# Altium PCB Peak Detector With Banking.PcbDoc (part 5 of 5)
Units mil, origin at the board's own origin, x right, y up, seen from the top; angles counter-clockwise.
Board outline 3330 x 2725 mil, 4 copper layers (TopLayer, GROUND, MidLayer1, BottomLayer); 549 components, 391 nets, 1594 pads, 460 vias.
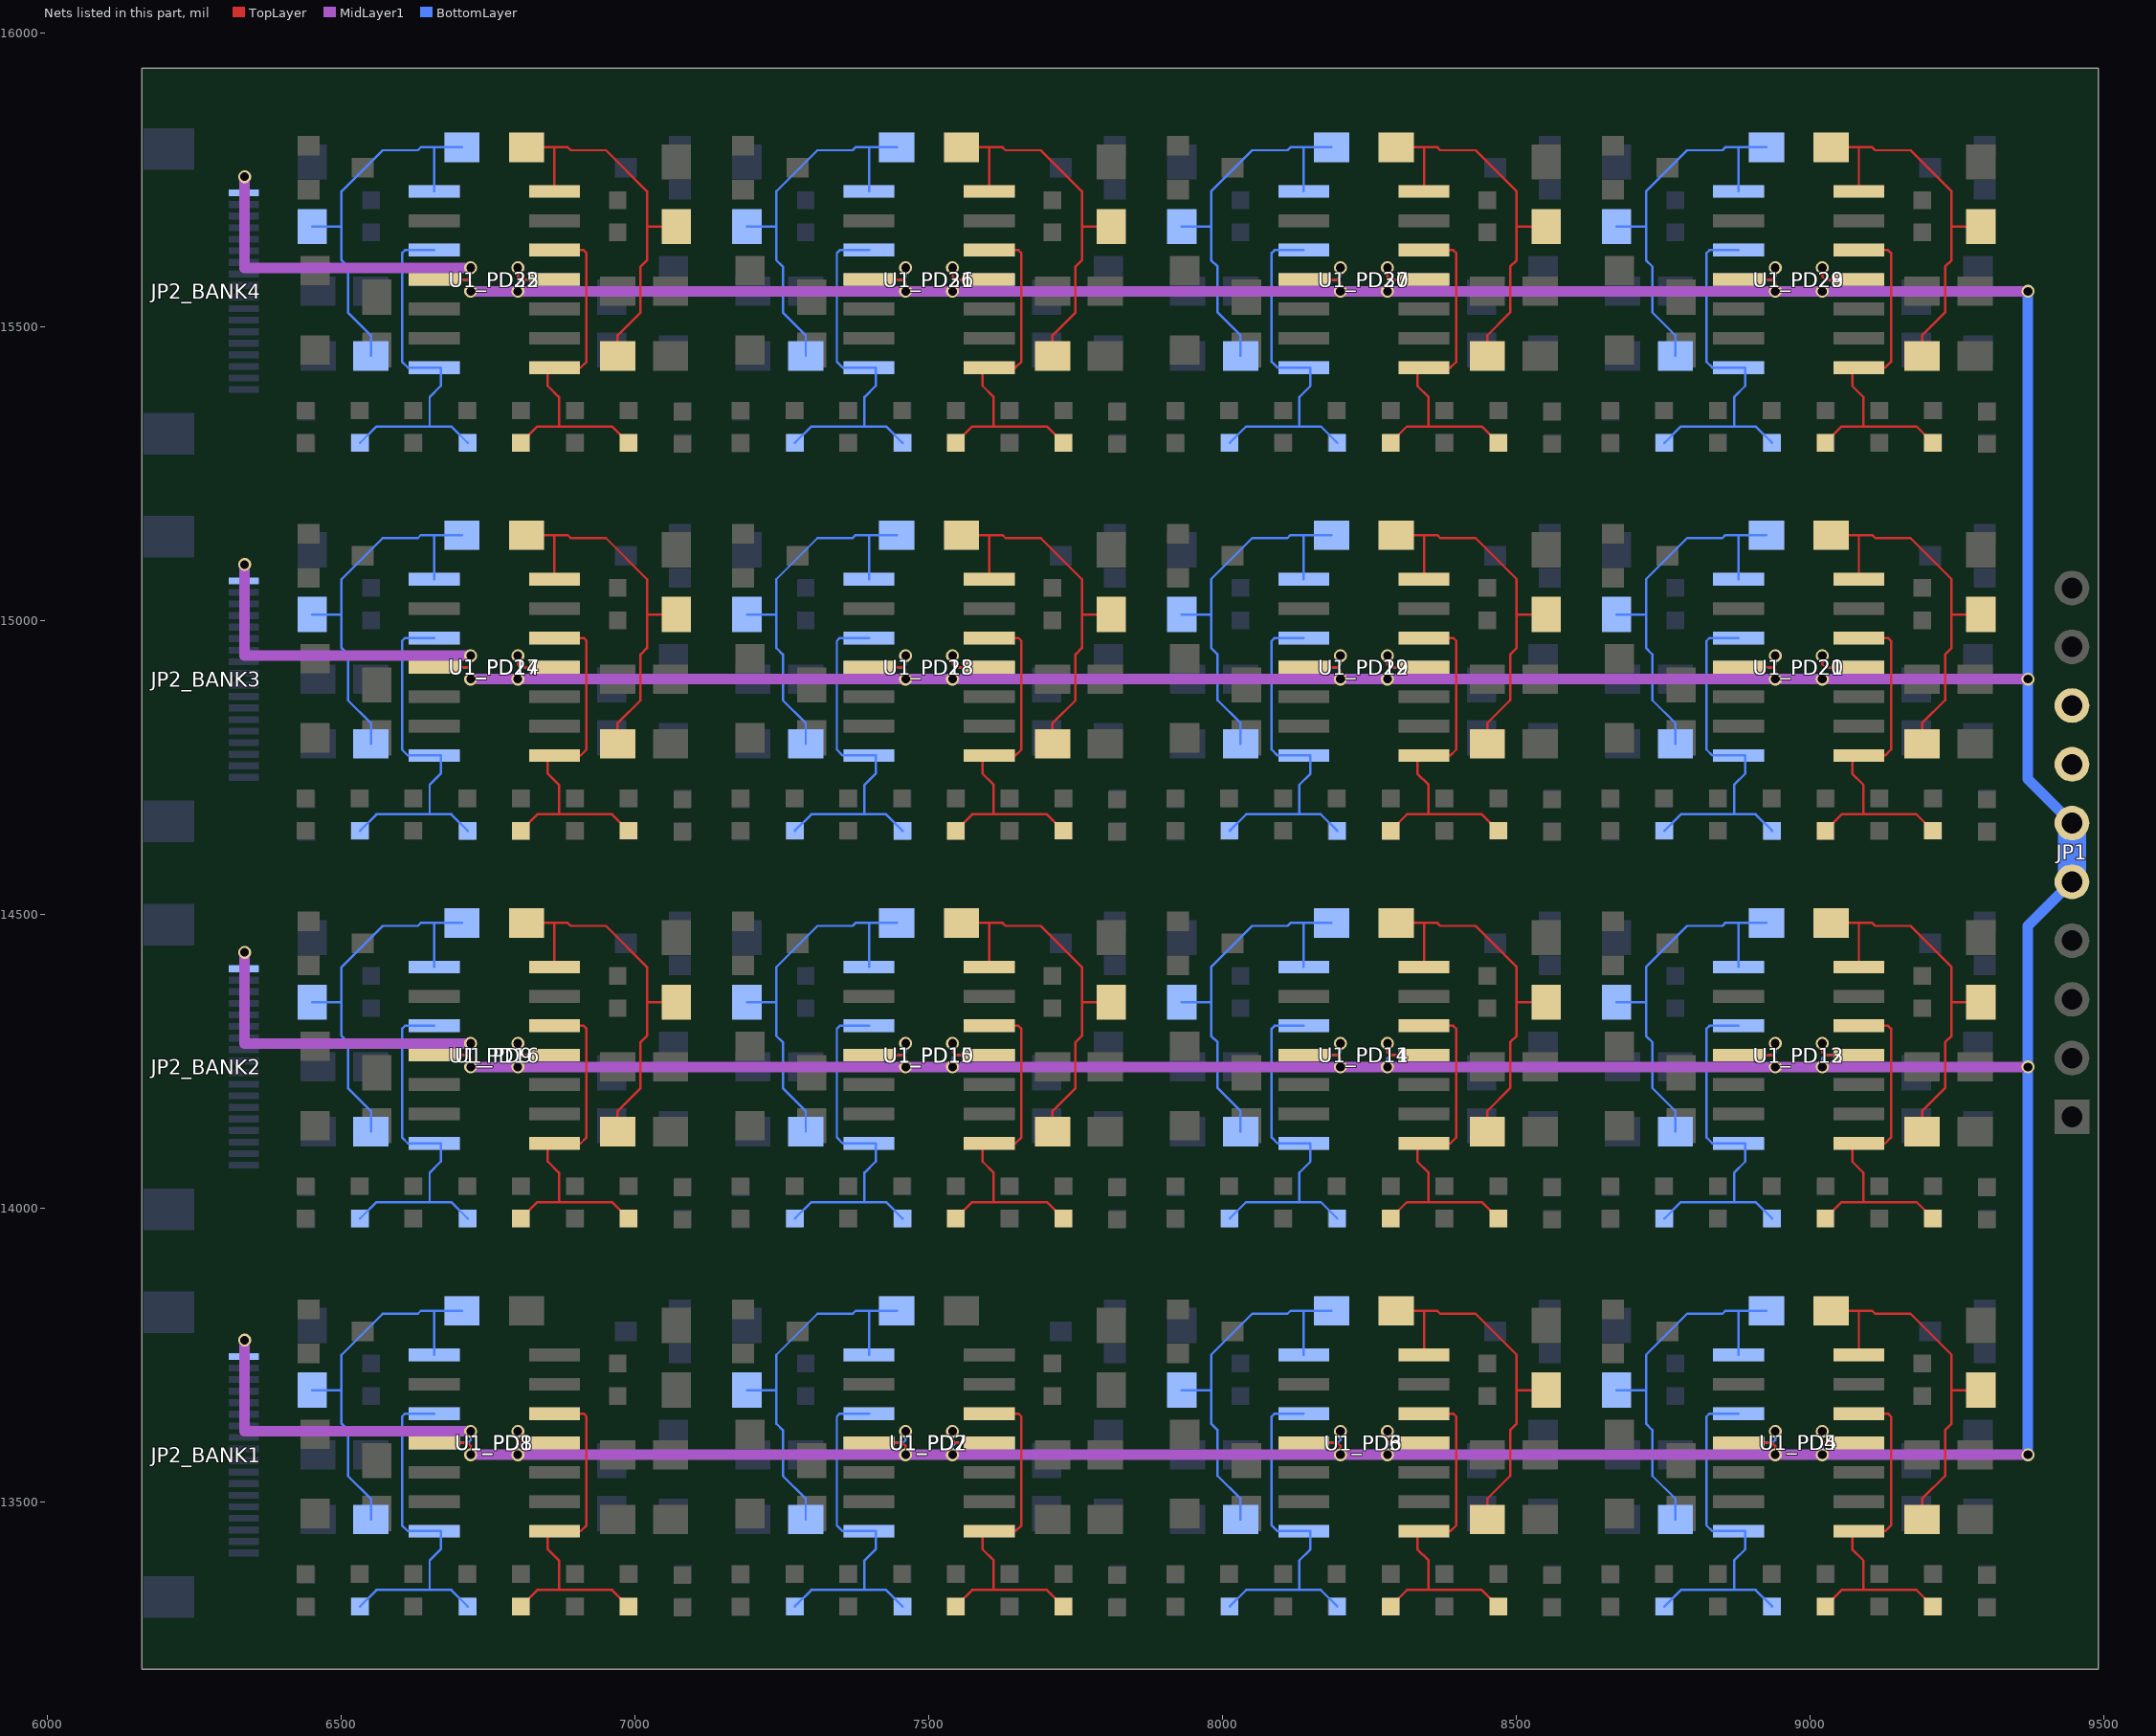
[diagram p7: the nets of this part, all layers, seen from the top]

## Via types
v1: diameter 22, hole 15, TopLayer to BottomLayer, 432 vias
v2: diameter 22, hole 16, TopLayer to BottomLayer, 28 vias

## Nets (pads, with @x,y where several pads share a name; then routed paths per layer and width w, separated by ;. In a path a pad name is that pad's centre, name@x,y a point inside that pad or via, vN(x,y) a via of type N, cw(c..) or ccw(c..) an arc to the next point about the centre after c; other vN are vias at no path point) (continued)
S_DIODE_PD3: C4_PD3.2 D1_PD3.1 D2_PD3.2 U1_PD3.7 | length 661.7
  TopLayer w4: D1_PD3.1@8295.01,13825 8342.35,13825 ; U1_PD3.7@8342.35,13750 8342.35,13825 ; C4_PD3.2@8449.99,13470 8449.99,13504.99 8489,13544 8489,13622 8500,13633 8500,13690 ; D2_PD3.2@8550,13690.01 8500.01,13690.01 ; 8342.35,13825 8365,13825 8370,13820 8430,13820 8500,13750 8500,13690.02
S_DIODE_PD4: C4_PD4.2 D1_PD4.1 D2_PD4.2 U1_PD4.7 | length 661.7
  TopLayer w4: D1_PD4.1@9035.01,13825 9082.35,13825 ; U1_PD4.7@9082.35,13750 9082.35,13825 ; C4_PD4.2@9189.99,13470 9189.99,13504.99 9229,13544 9229,13622 9240,13633 9240,13690 ; D2_PD4.2@9290,13690.01 9240.01,13690.01 ; 9082.35,13825 9105,13825 9110,13820 9170,13820 9240,13750 9240,13690.02
S_DIODE_PD5: C4_PD5.2 D1_PD5.1 D2_PD5.2 U1_PD5.7 | length 661.7
  BottomLayer w4: D2_PD5.2@8670,13690.01 8719.99,13690.01 ; C4_PD5.2@8770.01,13470 8770.01,13504.99 8731,13544 8731,13622 8720,13633 8720,13690 ; U1_PD5.7@8877.65,13750 8877.65,13825 ; D1_PD5.1@8924.99,13825 8877.65,13825 ; 8720,13690.02 8720,13750 8790,13820 8850,13820 8855,13825 8877.65,13825
S_DIODE_PD6: C4_PD6.2 D1_PD6.1 D2_PD6.2 U1_PD6.7 | length 661.7
  BottomLayer w4: D2_PD6.2@7930,13690.01 7979.99,13690.01 ; C4_PD6.2@8030.01,13470 8030.01,13504.99 7991,13544 7991,13622 7980,13633 7980,13690 ; U1_PD6.7@8137.65,13750 8137.65,13825 ; D1_PD6.1@8184.99,13825 8137.65,13825 ; 7980,13690.02 7980,13750 8050,13820 8110,13820 8115,13825 8137.65,13825
S_DIODE_PD7: C4_PD7.2 D1_PD7.1 D2_PD7.2 U1_PD7.7 | length 661.7
  BottomLayer w4: D2_PD7.2@7190,13690.01 7239.99,13690.01 ; C4_PD7.2@7290.01,13470 7290.01,13504.99 7251,13544 7251,13622 7240,13633 7240,13690 ; U1_PD7.7@7397.65,13750 7397.65,13825 ; D1_PD7.1@7444.99,13825 7397.65,13825 ; 7240,13690.02 7240,13750 7310,13820 7370,13820 7375,13825 7397.65,13825
S_DIODE_PD8: C4_PD8.2 D1_PD8.1 D2_PD8.2 U1_PD8.7 | length 661.7
  BottomLayer w4: D2_PD8.2@6450,13690.01 6499.99,13690.01 ; C4_PD8.2@6550.01,13470 6550.01,13504.99 6511,13544 6511,13622 6500,13633 6500,13690 ; U1_PD8.7@6657.65,13750 6657.65,13825 ; D1_PD8.1@6704.99,13825 6657.65,13825 ; 6500,13690.02 6500,13750 6570,13820 6630,13820 6635,13825 6657.65,13825
S_DIODE_PD9: C4_PD9.2 D1_PD9.1 D2_PD9.2 U1_PD9.7 | length 661.7
  TopLayer w4: D1_PD9.1@6815.01,14485 6862.35,14485 ; U1_PD9.7@6862.35,14410 6862.35,14485 ; C4_PD9.2@6969.99,14130 6969.99,14164.99 7009,14204 7009,14282 7020,14293 7020,14350 ; D2_PD9.2@7070,14350.01 7020.01,14350.01 ; 6862.35,14485 6885,14485 6890,14480 6950,14480 7020,14410 7020,14350.02
S_DIODE_PD10: C4_PD10.2 D1_PD10.1 D2_PD10.2 U1_PD10.7 | length 661.7
  TopLayer w4: D1_PD10.1@7555.01,14485 7602.35,14485 ; U1_PD10.7@7602.35,14410 7602.35,14485 ; C4_PD10.2@7709.99,14130 7709.99,14164.99 7749,14204 7749,14282 7760,14293 7760,14350 ; D2_PD10.2@7810,14350.01 7760.01,14350.01 ; 7602.35,14485 7625,14485 7630,14480 7690,14480 7760,14410 7760,14350.02
S_DIODE_PD11: C4_PD11.2 D1_PD11.1 D2_PD11.2 U1_PD11.7 | length 661.7
  TopLayer w4: D1_PD11.1@8295.01,14485 8342.35,14485 ; U1_PD11.7@8342.35,14410 8342.35,14485 ; C4_PD11.2@8449.99,14130 8449.99,14164.99 8489,14204 8489,14282 8500,14293 8500,14350 ; D2_PD11.2@8550,14350.01 8500.01,14350.01 ; 8342.35,14485 8365,14485 8370,14480 8430,14480 8500,14410 8500,14350.02
S_DIODE_PD12: C4_PD12.2 D1_PD12.1 D2_PD12.2 U1_PD12.7 | length 661.7
  TopLayer w4: D1_PD12.1@9035.01,14485 9082.35,14485 ; U1_PD12.7@9082.35,14410 9082.35,14485 ; C4_PD12.2@9189.99,14130 9189.99,14164.99 9229,14204 9229,14282 9240,14293 9240,14350 ; D2_PD12.2@9290,14350.01 9240.01,14350.01 ; 9082.35,14485 9105,14485 9110,14480 9170,14480 9240,14410 9240,14350.02
S_DIODE_PD13: C4_PD13.2 D1_PD13.1 D2_PD13.2 U1_PD13.7 | length 661.7
  BottomLayer w4: D2_PD13.2@8670,14350.01 8719.99,14350.01 ; C4_PD13.2@8770.01,14130 8770.01,14164.99 8731,14204 8731,14282 8720,14293 8720,14350 ; U1_PD13.7@8877.65,14410 8877.65,14485 ; D1_PD13.1@8924.99,14485 8877.65,14485 ; 8720,14350.02 8720,14410 8790,14480 8850,14480 8855,14485 8877.65,14485
S_DIODE_PD14: C4_PD14.2 D1_PD14.1 D2_PD14.2 U1_PD14.7 | length 661.7
  BottomLayer w4: D2_PD14.2@7930,14350.01 7979.99,14350.01 ; C4_PD14.2@8030.01,14130 8030.01,14164.99 7991,14204 7991,14282 7980,14293 7980,14350 ; U1_PD14.7@8137.65,14410 8137.65,14485 ; D1_PD14.1@8184.99,14485 8137.65,14485 ; 7980,14350.02 7980,14410 8050,14480 8110,14480 8115,14485 8137.65,14485
S_DIODE_PD15: C4_PD15.2 D1_PD15.1 D2_PD15.2 U1_PD15.7 | length 661.7
  BottomLayer w4: D2_PD15.2@7190,14350.01 7239.99,14350.01 ; C4_PD15.2@7290.01,14130 7290.01,14164.99 7251,14204 7251,14282 7240,14293 7240,14350 ; U1_PD15.7@7397.65,14410 7397.65,14485 ; D1_PD15.1@7444.99,14485 7397.65,14485 ; 7240,14350.02 7240,14410 7310,14480 7370,14480 7375,14485 7397.65,14485
S_DIODE_PD16: C4_PD16.2 D1_PD16.1 D2_PD16.2 U1_PD16.7 | length 661.7
  BottomLayer w4: D2_PD16.2@6450,14350.01 6499.99,14350.01 ; C4_PD16.2@6550.01,14130 6550.01,14164.99 6511,14204 6511,14282 6500,14293 6500,14350 ; U1_PD16.7@6657.65,14410 6657.65,14485 ; D1_PD16.1@6704.99,14485 6657.65,14485 ; 6500,14350.02 6500,14410 6570,14480 6630,14480 6635,14485 6657.65,14485
S_DIODE_PD17: C4_PD17.2 D1_PD17.1 D2_PD17.2 U1_PD17.7 | length 661.7
  TopLayer w4: D1_PD17.1@6815.01,15145 6862.35,15145 ; U1_PD17.7@6862.35,15070 6862.35,15145 ; C4_PD17.2@6969.99,14790 6969.99,14824.99 7009,14864 7009,14942 7020,14953 7020,15010 ; D2_PD17.2@7070,15010.01 7020.01,15010.01 ; 6862.35,15145 6885,15145 6890,15140 6950,15140 7020,15070 7020,15010.02
S_DIODE_PD18: C4_PD18.2 D1_PD18.1 D2_PD18.2 U1_PD18.7 | length 661.7
  TopLayer w4: D1_PD18.1@7555.01,15145 7602.35,15145 ; U1_PD18.7@7602.35,15070 7602.35,15145 ; C4_PD18.2@7709.99,14790 7709.99,14824.99 7749,14864 7749,14942 7760,14953 7760,15010 ; D2_PD18.2@7810,15010.01 7760.01,15010.01 ; 7602.35,15145 7625,15145 7630,15140 7690,15140 7760,15070 7760,15010.02
S_DIODE_PD19: C4_PD19.2 D1_PD19.1 D2_PD19.2 U1_PD19.7 | length 661.7
  TopLayer w4: D1_PD19.1@8295.01,15145 8342.35,15145 ; U1_PD19.7@8342.35,15070 8342.35,15145 ; C4_PD19.2@8449.99,14790 8449.99,14824.99 8489,14864 8489,14942 8500,14953 8500,15010 ; D2_PD19.2@8550,15010.01 8500.01,15010.01 ; 8342.35,15145 8365,15145 8370,15140 8430,15140 8500,15070 8500,15010.02
S_DIODE_PD20: C4_PD20.2 D1_PD20.1 D2_PD20.2 U1_PD20.7 | length 661.7
  TopLayer w4: D1_PD20.1@9035.01,15145 9082.35,15145 ; U1_PD20.7@9082.35,15070 9082.35,15145 ; C4_PD20.2@9189.99,14790 9189.99,14824.99 9229,14864 9229,14942 9240,14953 9240,15010 ; D2_PD20.2@9290,15010.01 9240.01,15010.01 ; 9082.35,15145 9105,15145 9110,15140 9170,15140 9240,15070 9240,15010.02
S_DIODE_PD21: C4_PD21.2 D1_PD21.1 D2_PD21.2 U1_PD21.7 | length 661.7
  BottomLayer w4: D2_PD21.2@8670,15010.01 8719.99,15010.01 ; C4_PD21.2@8770.01,14790 8770.01,14824.99 8731,14864 8731,14942 8720,14953 8720,15010 ; U1_PD21.7@8877.65,15070 8877.65,15145 ; D1_PD21.1@8924.99,15145 8877.65,15145 ; 8720,15010.02 8720,15070 8790,15140 8850,15140 8855,15145 8877.65,15145
S_DIODE_PD22: C4_PD22.2 D1_PD22.1 D2_PD22.2 U1_PD22.7 | length 661.7
  BottomLayer w4: D2_PD22.2@7930,15010.01 7979.99,15010.01 ; C4_PD22.2@8030.01,14790 8030.01,14824.99 7991,14864 7991,14942 7980,14953 7980,15010 ; U1_PD22.7@8137.65,15070 8137.65,15145 ; D1_PD22.1@8184.99,15145 8137.65,15145 ; 7980,15010.02 7980,15070 8050,15140 8110,15140 8115,15145 8137.65,15145
S_DIODE_PD23: C4_PD23.2 D1_PD23.1 D2_PD23.2 U1_PD23.7 | length 661.7
  BottomLayer w4: D2_PD23.2@7190,15010.01 7239.99,15010.01 ; C4_PD23.2@7290.01,14790 7290.01,14824.99 7251,14864 7251,14942 7240,14953 7240,15010 ; U1_PD23.7@7397.65,15070 7397.65,15145 ; D1_PD23.1@7444.99,15145 7397.65,15145 ; 7240,15010.02 7240,15070 7310,15140 7370,15140 7375,15145 7397.65,15145
S_DIODE_PD24: C4_PD24.2 D1_PD24.1 D2_PD24.2 U1_PD24.7 | length 661.7
  BottomLayer w4: D2_PD24.2@6450,15010.01 6499.99,15010.01 ; C4_PD24.2@6550.01,14790 6550.01,14824.99 6511,14864 6511,14942 6500,14953 6500,15010 ; U1_PD24.7@6657.65,15070 6657.65,15145 ; D1_PD24.1@6704.99,15145 6657.65,15145 ; 6500,15010.02 6500,15070 6570,15140 6630,15140 6635,15145 6657.65,15145
S_DIODE_PD25: C4_PD25.2 D1_PD25.1 D2_PD25.2 U1_PD25.7 | length 661.7
  TopLayer w4: D1_PD25.1@6815.01,15805 6862.35,15805 ; U1_PD25.7@6862.35,15730 6862.35,15805 ; C4_PD25.2@6969.99,15450 6969.99,15484.99 7009,15524 7009,15602 7020,15613 7020,15670 ; D2_PD25.2@7070,15670.01 7020.01,15670.01 ; 6862.35,15805 6885,15805 6890,15800 6950,15800 7020,15730 7020,15670.02
S_DIODE_PD26: C4_PD26.2 D1_PD26.1 D2_PD26.2 U1_PD26.7 | length 661.7
  TopLayer w4: D1_PD26.1@7555.01,15805 7602.35,15805 ; U1_PD26.7@7602.35,15730 7602.35,15805 ; C4_PD26.2@7709.99,15450 7709.99,15484.99 7749,15524 7749,15602 7760,15613 7760,15670 ; D2_PD26.2@7810,15670.01 7760.01,15670.01 ; 7602.35,15805 7625,15805 7630,15800 7690,15800 7760,15730 7760,15670.02
S_DIODE_PD27: C4_PD27.2 D1_PD27.1 D2_PD27.2 U1_PD27.7 | length 661.7
  TopLayer w4: D1_PD27.1@8295.01,15805 8342.35,15805 ; U1_PD27.7@8342.35,15730 8342.35,15805 ; C4_PD27.2@8449.99,15450 8449.99,15484.99 8489,15524 8489,15602 8500,15613 8500,15670 ; D2_PD27.2@8550,15670.01 8500.01,15670.01 ; 8342.35,15805 8365,15805 8370,15800 8430,15800 8500,15730 8500,15670.02
S_DIODE_PD28: C4_PD28.2 D1_PD28.1 D2_PD28.2 U1_PD28.7 | length 661.7
  TopLayer w4: D1_PD28.1@9035.01,15805 9082.35,15805 ; U1_PD28.7@9082.35,15730 9082.35,15805 ; C4_PD28.2@9189.99,15450 9189.99,15484.99 9229,15524 9229,15602 9240,15613 9240,15670 ; D2_PD28.2@9290,15670.01 9240.01,15670.01 ; 9082.35,15805 9105,15805 9110,15800 9170,15800 9240,15730 9240,15670.02
S_DIODE_PD29: C4_PD29.2 D1_PD29.1 D2_PD29.2 U1_PD29.7 | length 661.7
  BottomLayer w4: D2_PD29.2@8670,15670.01 8719.99,15670.01 ; C4_PD29.2@8770.01,15450 8770.01,15484.99 8731,15524 8731,15602 8720,15613 8720,15670 ; U1_PD29.7@8877.65,15730 8877.65,15805 ; D1_PD29.1@8924.99,15805 8877.65,15805 ; 8720,15670.02 8720,15730 8790,15800 8850,15800 8855,15805 8877.65,15805
S_DIODE_PD30: C4_PD30.2 D1_PD30.1 D2_PD30.2 U1_PD30.7 | length 661.7
  BottomLayer w4: D2_PD30.2@7930,15670.01 7979.99,15670.01 ; C4_PD30.2@8030.01,15450 8030.01,15484.99 7991,15524 7991,15602 7980,15613 7980,15670 ; U1_PD30.7@8137.65,15730 8137.65,15805 ; D1_PD30.1@8184.99,15805 8137.65,15805 ; 7980,15670.02 7980,15730 8050,15800 8110,15800 8115,15805 8137.65,15805
S_DIODE_PD31: C4_PD31.2 D1_PD31.1 D2_PD31.2 U1_PD31.7 | length 661.7
  BottomLayer w4: D2_PD31.2@7190,15670.01 7239.99,15670.01 ; C4_PD31.2@7290.01,15450 7290.01,15484.99 7251,15524 7251,15602 7240,15613 7240,15670 ; U1_PD31.7@7397.65,15730 7397.65,15805 ; D1_PD31.1@7444.99,15805 7397.65,15805 ; 7240,15670.02 7240,15730 7310,15800 7370,15800 7375,15805 7397.65,15805
S_DIODE_PD32: C4_PD32.2 D1_PD32.1 D2_PD32.2 U1_PD32.7 | length 661.7
  BottomLayer w4: D2_PD32.2@6450,15670.01 6499.99,15670.01 ; C4_PD32.2@6550.01,15450 6550.01,15484.99 6511,15524 6511,15602 6500,15613 6500,15670 ; U1_PD32.7@6657.65,15730 6657.65,15805 ; D1_PD32.1@6704.99,15805 6657.65,15805 ; 6500,15670.02 6500,15730 6570,15800 6630,15800 6635,15805 6657.65,15805
TRACKING_PD1: R6_PD1.1 RPOT_PD1.2 U1_PD1.1 U1_PD1.5 | length 625.1
  TopLayer w4: RPOT_PD1.2@6805.29,13321.99 6833.3,13350 6850,13350 ; 6851,13350 6870,13350 ; U1_PD1.5@6862.35,13650 6912,13650 6917,13645 6917,13460 6907,13450 U1_PD1.1@6862.35,13450 6851,13450 6851,13419 6870,13400 6870,13350 ; R6_PD1.1@6988.43,13322 6960.43,13350 6870,13350
TRACKING_PD2: R6_PD2.1 RPOT_PD2.2 U1_PD2.1 U1_PD2.5 | length 625.1
  TopLayer w4: RPOT_PD2.2@7545.29,13321.99 7573.3,13350 7590,13350 ; 7591,13350 7610,13350 ; U1_PD2.5@7602.35,13650 7652,13650 7657,13645 7657,13460 7647,13450 U1_PD2.1@7602.35,13450 7591,13450 7591,13419 7610,13400 7610,13350 ; R6_PD2.1@7728.43,13322 7700.43,13350 7610,13350
TRACKING_PD3: R6_PD3.1 RPOT_PD3.2 U1_PD3.1 U1_PD3.5 | length 625.1
  TopLayer w4: RPOT_PD3.2@8285.29,13321.99 8313.3,13350 8330,13350 ; 8331,13350 8350,13350 ; U1_PD3.5@8342.35,13650 8392,13650 8397,13645 8397,13460 8387,13450 U1_PD3.1@8342.35,13450 8331,13450 8331,13419 8350,13400 8350,13350 ; R6_PD3.1@8468.43,13322 8440.43,13350 8350,13350
TRACKING_PD4: R6_PD4.1 RPOT_PD4.2 U1_PD4.1 U1_PD4.5 | length 625.1
  TopLayer w4: RPOT_PD4.2@9025.29,13321.99 9053.3,13350 9070,13350 ; 9071,13350 9090,13350 ; U1_PD4.5@9082.35,13650 9132,13650 9137,13645 9137,13460 9127,13450 U1_PD4.1@9082.35,13450 9071,13450 9071,13419 9090,13400 9090,13350 ; R6_PD4.1@9208.43,13322 9180.43,13350 9090,13350
TRACKING_PD5: R6_PD5.1 RPOT_PD5.2 U1_PD5.1 U1_PD5.5 | length 625.1
  BottomLayer w4: R6_PD5.1@8751.57,13322 8779.57,13350 8870,13350 ; U1_PD5.5@8877.65,13650 8828,13650 8823,13645 8823,13460 8833,13450 U1_PD5.1@8877.65,13450 8889,13450 8889,13419 8870,13400 8870,13350 ; 8889,13350 8870,13350 ; 8890,13350 8906.7,13350 RPOT_PD5.2@8934.71,13321.99
TRACKING_PD6: R6_PD6.1 RPOT_PD6.2 U1_PD6.1 U1_PD6.5 | length 625.1
  BottomLayer w4: R6_PD6.1@8011.57,13322 8039.57,13350 8130,13350 ; U1_PD6.5@8137.65,13650 8088,13650 8083,13645 8083,13460 8093,13450 U1_PD6.1@8137.65,13450 8149,13450 8149,13419 8130,13400 8130,13350 ; 8149,13350 8130,13350 ; 8150,13350 8166.7,13350 RPOT_PD6.2@8194.71,13321.99
TRACKING_PD7: R6_PD7.1 RPOT_PD7.2 U1_PD7.1 U1_PD7.5 | length 625.1
  BottomLayer w4: R6_PD7.1@7271.57,13322 7299.57,13350 7390,13350 ; U1_PD7.5@7397.65,13650 7348,13650 7343,13645 7343,13460 7353,13450 U1_PD7.1@7397.65,13450 7409,13450 7409,13419 7390,13400 7390,13350 ; 7409,13350 7390,13350 ; 7410,13350 7426.7,13350 RPOT_PD7.2@7454.71,13321.99
TRACKING_PD8: R6_PD8.1 RPOT_PD8.2 U1_PD8.1 U1_PD8.5 | length 625.1
  BottomLayer w4: R6_PD8.1@6531.57,13322 6559.57,13350 6650,13350 ; U1_PD8.5@6657.65,13650 6608,13650 6603,13645 6603,13460 6613,13450 U1_PD8.1@6657.65,13450 6669,13450 6669,13419 6650,13400 6650,13350 ; 6669,13350 6650,13350 ; 6670,13350 6686.7,13350 RPOT_PD8.2@6714.71,13321.99
TRACKING_PD9: R6_PD9.1 RPOT_PD9.2 U1_PD9.1 U1_PD9.5 | length 625.1
  TopLayer w4: RPOT_PD9.2@6805.29,13981.99 6833.3,14010 6850,14010 ; 6851,14010 6870,14010 ; U1_PD9.5@6862.35,14310 6912,14310 6917,14305 6917,14120 6907,14110 U1_PD9.1@6862.35,14110 6851,14110 6851,14079 6870,14060 6870,14010 ; R6_PD9.1@6988.43,13982 6960.43,14010 6870,14010
TRACKING_PD10: R6_PD10.1 RPOT_PD10.2 U1_PD10.1 U1_PD10.5 | length 625.1
  TopLayer w4: RPOT_PD10.2@7545.29,13981.99 7573.3,14010 7590,14010 ; 7591,14010 7610,14010 ; U1_PD10.5@7602.35,14310 7652,14310 7657,14305 7657,14120 7647,14110 U1_PD10.1@7602.35,14110 7591,14110 7591,14079 7610,14060 7610,14010 ; R6_PD10.1@7728.43,13982 7700.43,14010 7610,14010
TRACKING_PD11: R6_PD11.1 RPOT_PD11.2 U1_PD11.1 U1_PD11.5 | length 625.1
  TopLayer w4: RPOT_PD11.2@8285.29,13981.99 8313.3,14010 8330,14010 ; 8331,14010 8350,14010 ; U1_PD11.5@8342.35,14310 8392,14310 8397,14305 8397,14120 8387,14110 U1_PD11.1@8342.35,14110 8331,14110 8331,14079 8350,14060 8350,14010 ; R6_PD11.1@8468.43,13982 8440.43,14010 8350,14010
TRACKING_PD12: R6_PD12.1 RPOT_PD12.2 U1_PD12.1 U1_PD12.5 | length 625.1
  TopLayer w4: RPOT_PD12.2@9025.29,13981.99 9053.3,14010 9070,14010 ; 9071,14010 9090,14010 ; U1_PD12.5@9082.35,14310 9132,14310 9137,14305 9137,14120 9127,14110 U1_PD12.1@9082.35,14110 9071,14110 9071,14079 9090,14060 9090,14010 ; R6_PD12.1@9208.43,13982 9180.43,14010 9090,14010
TRACKING_PD13: R6_PD13.1 RPOT_PD13.2 U1_PD13.1 U1_PD13.5 | length 625.1
  BottomLayer w4: R6_PD13.1@8751.57,13982 8779.57,14010 8870,14010 ; U1_PD13.5@8877.65,14310 8828,14310 8823,14305 8823,14120 8833,14110 U1_PD13.1@8877.65,14110 8889,14110 8889,14079 8870,14060 8870,14010 ; 8889,14010 8870,14010 ; 8890,14010 8906.7,14010 RPOT_PD13.2@8934.71,13981.99
TRACKING_PD14: R6_PD14.1 RPOT_PD14.2 U1_PD14.1 U1_PD14.5 | length 625.1
  BottomLayer w4: R6_PD14.1@8011.57,13982 8039.57,14010 8130,14010 ; U1_PD14.5@8137.65,14310 8088,14310 8083,14305 8083,14120 8093,14110 U1_PD14.1@8137.65,14110 8149,14110 8149,14079 8130,14060 8130,14010 ; 8149,14010 8130,14010 ; 8150,14010 8166.7,14010 RPOT_PD14.2@8194.71,13981.99
TRACKING_PD15: R6_PD15.1 RPOT_PD15.2 U1_PD15.1 U1_PD15.5 | length 625.1
  BottomLayer w4: R6_PD15.1@7271.57,13982 7299.57,14010 7390,14010 ; U1_PD15.5@7397.65,14310 7348,14310 7343,14305 7343,14120 7353,14110 U1_PD15.1@7397.65,14110 7409,14110 7409,14079 7390,14060 7390,14010 ; 7409,14010 7390,14010 ; 7410,14010 7426.7,14010 RPOT_PD15.2@7454.71,13981.99
TRACKING_PD16: R6_PD16.1 RPOT_PD16.2 U1_PD16.1 U1_PD16.5 | length 625.1
  BottomLayer w4: R6_PD16.1@6531.57,13982 6559.57,14010 6650,14010 ; U1_PD16.5@6657.65,14310 6608,14310 6603,14305 6603,14120 6613,14110 U1_PD16.1@6657.65,14110 6669,14110 6669,14079 6650,14060 6650,14010 ; 6669,14010 6650,14010 ; 6670,14010 6686.7,14010 RPOT_PD16.2@6714.71,13981.99
TRACKING_PD17: R6_PD17.1 RPOT_PD17.2 U1_PD17.1 U1_PD17.5 | length 625.1
  TopLayer w4: RPOT_PD17.2@6805.29,14641.99 6833.3,14670 6850,14670 ; 6851,14670 6870,14670 ; U1_PD17.5@6862.35,14970 6912,14970 6917,14965 6917,14780 6907,14770 U1_PD17.1@6862.35,14770 6851,14770 6851,14739 6870,14720 6870,14670 ; R6_PD17.1@6988.43,14642 6960.43,14670 6870,14670
TRACKING_PD18: R6_PD18.1 RPOT_PD18.2 U1_PD18.1 U1_PD18.5 | length 625.1
  TopLayer w4: RPOT_PD18.2@7545.29,14641.99 7573.3,14670 7590,14670 ; 7591,14670 7610,14670 ; U1_PD18.5@7602.35,14970 7652,14970 7657,14965 7657,14780 7647,14770 U1_PD18.1@7602.35,14770 7591,14770 7591,14739 7610,14720 7610,14670 ; R6_PD18.1@7728.43,14642 7700.43,14670 7610,14670
TRACKING_PD19: R6_PD19.1 RPOT_PD19.2 U1_PD19.1 U1_PD19.5 | length 625.1
  TopLayer w4: RPOT_PD19.2@8285.29,14641.99 8313.3,14670 8330,14670 ; 8331,14670 8350,14670 ; U1_PD19.5@8342.35,14970 8392,14970 8397,14965 8397,14780 8387,14770 U1_PD19.1@8342.35,14770 8331,14770 8331,14739 8350,14720 8350,14670 ; R6_PD19.1@8468.43,14642 8440.43,14670 8350,14670
TRACKING_PD20: R6_PD20.1 RPOT_PD20.2 U1_PD20.1 U1_PD20.5 | length 625.1
  TopLayer w4: RPOT_PD20.2@9025.29,14641.99 9053.3,14670 9070,14670 ; 9071,14670 9090,14670 ; U1_PD20.5@9082.35,14970 9132,14970 9137,14965 9137,14780 9127,14770 U1_PD20.1@9082.35,14770 9071,14770 9071,14739 9090,14720 9090,14670 ; R6_PD20.1@9208.43,14642 9180.43,14670 9090,14670
TRACKING_PD21: R6_PD21.1 RPOT_PD21.2 U1_PD21.1 U1_PD21.5 | length 625.1
  BottomLayer w4: R6_PD21.1@8751.57,14642 8779.57,14670 8870,14670 ; U1_PD21.5@8877.65,14970 8828,14970 8823,14965 8823,14780 8833,14770 U1_PD21.1@8877.65,14770 8889,14770 8889,14739 8870,14720 8870,14670 ; 8889,14670 8870,14670 ; 8890,14670 8906.7,14670 RPOT_PD21.2@8934.71,14641.99
TRACKING_PD22: R6_PD22.1 RPOT_PD22.2 U1_PD22.1 U1_PD22.5 | length 625.1
  BottomLayer w4: R6_PD22.1@8011.57,14642 8039.57,14670 8130,14670 ; U1_PD22.5@8137.65,14970 8088,14970 8083,14965 8083,14780 8093,14770 U1_PD22.1@8137.65,14770 8149,14770 8149,14739 8130,14720 8130,14670 ; 8149,14670 8130,14670 ; 8150,14670 8166.7,14670 RPOT_PD22.2@8194.71,14641.99
TRACKING_PD23: R6_PD23.1 RPOT_PD23.2 U1_PD23.1 U1_PD23.5 | length 625.1
  BottomLayer w4: R6_PD23.1@7271.57,14642 7299.57,14670 7390,14670 ; U1_PD23.5@7397.65,14970 7348,14970 7343,14965 7343,14780 7353,14770 U1_PD23.1@7397.65,14770 7409,14770 7409,14739 7390,14720 7390,14670 ; 7409,14670 7390,14670 ; 7410,14670 7426.7,14670 RPOT_PD23.2@7454.71,14641.99
TRACKING_PD24: R6_PD24.1 RPOT_PD24.2 U1_PD24.1 U1_PD24.5 | length 625.1
  BottomLayer w4: R6_PD24.1@6531.57,14642 6559.57,14670 6650,14670 ; U1_PD24.5@6657.65,14970 6608,14970 6603,14965 6603,14780 6613,14770 U1_PD24.1@6657.65,14770 6669,14770 6669,14739 6650,14720 6650,14670 ; 6669,14670 6650,14670 ; 6670,14670 6686.7,14670 RPOT_PD24.2@6714.71,14641.99
TRACKING_PD25: R6_PD25.1 RPOT_PD25.2 U1_PD25.1 U1_PD25.5 | length 625.1
  TopLayer w4: RPOT_PD25.2@6805.29,15301.99 6833.3,15330 6850,15330 ; 6851,15330 6870,15330 ; U1_PD25.5@6862.35,15630 6912,15630 6917,15625 6917,15440 6907,15430 U1_PD25.1@6862.35,15430 6851,15430 6851,15399 6870,15380 6870,15330 ; R6_PD25.1@6988.43,15302 6960.43,15330 6870,15330
TRACKING_PD26: R6_PD26.1 RPOT_PD26.2 U1_PD26.1 U1_PD26.5 | length 625.1
  TopLayer w4: RPOT_PD26.2@7545.29,15301.99 7573.3,15330 7590,15330 ; 7591,15330 7610,15330 ; U1_PD26.5@7602.35,15630 7652,15630 7657,15625 7657,15440 7647,15430 U1_PD26.1@7602.35,15430 7591,15430 7591,15399 7610,15380 7610,15330 ; R6_PD26.1@7728.43,15302 7700.43,15330 7610,15330
TRACKING_PD27: R6_PD27.1 RPOT_PD27.2 U1_PD27.1 U1_PD27.5 | length 625.1
  TopLayer w4: RPOT_PD27.2@8285.29,15301.99 8313.3,15330 8330,15330 ; 8331,15330 8350,15330 ; U1_PD27.5@8342.35,15630 8392,15630 8397,15625 8397,15440 8387,15430 U1_PD27.1@8342.35,15430 8331,15430 8331,15399 8350,15380 8350,15330 ; R6_PD27.1@8468.43,15302 8440.43,15330 8350,15330
TRACKING_PD28: R6_PD28.1 RPOT_PD28.2 U1_PD28.1 U1_PD28.5 | length 625.1
  TopLayer w4: RPOT_PD28.2@9025.29,15301.99 9053.3,15330 9070,15330 ; 9071,15330 9090,15330 ; U1_PD28.5@9082.35,15630 9132,15630 9137,15625 9137,15440 9127,15430 U1_PD28.1@9082.35,15430 9071,15430 9071,15399 9090,15380 9090,15330 ; R6_PD28.1@9208.43,15302 9180.43,15330 9090,15330
TRACKING_PD29: R6_PD29.1 RPOT_PD29.2 U1_PD29.1 U1_PD29.5 | length 625.1
  BottomLayer w4: R6_PD29.1@8751.57,15302 8779.57,15330 8870,15330 ; U1_PD29.5@8877.65,15630 8828,15630 8823,15625 8823,15440 8833,15430 U1_PD29.1@8877.65,15430 8889,15430 8889,15399 8870,15380 8870,15330 ; 8889,15330 8870,15330 ; 8890,15330 8906.7,15330 RPOT_PD29.2@8934.71,15301.99
TRACKING_PD30: R6_PD30.1 RPOT_PD30.2 U1_PD30.1 U1_PD30.5 | length 625.1
  BottomLayer w4: R6_PD30.1@8011.57,15302 8039.57,15330 8130,15330 ; U1_PD30.5@8137.65,15630 8088,15630 8083,15625 8083,15440 8093,15430 U1_PD30.1@8137.65,15430 8149,15430 8149,15399 8130,15380 8130,15330 ; 8149,15330 8130,15330 ; 8150,15330 8166.7,15330 RPOT_PD30.2@8194.71,15301.99
TRACKING_PD31: R6_PD31.1 RPOT_PD31.2 U1_PD31.1 U1_PD31.5 | length 625.1
  BottomLayer w4: R6_PD31.1@7271.57,15302 7299.57,15330 7390,15330 ; U1_PD31.5@7397.65,15630 7348,15630 7343,15625 7343,15440 7353,15430 U1_PD31.1@7397.65,15430 7409,15430 7409,15399 7390,15380 7390,15330 ; 7409,15330 7390,15330 ; 7410,15330 7426.7,15330 RPOT_PD31.2@7454.71,15301.99
TRACKING_PD32: R6_PD32.1 RPOT_PD32.2 U1_PD32.1 U1_PD32.5 | length 625.1
  BottomLayer w4: R6_PD32.1@6531.57,15302 6559.57,15330 6650,15330 ; U1_PD32.5@6657.65,15630 6608,15630 6603,15625 6603,15440 6613,15430 U1_PD32.1@6657.65,15430 6669,15430 6669,15399 6650,15380 6650,15330 ; 6669,15330 6650,15330 ; 6670,15330 6686.7,15330 RPOT_PD32.2@6714.71,15301.99
VCC5: JP1.7 JP1.8 JP2_BANK1.18 JP2_BANK2.18 JP2_BANK3.18 JP2_BANK4.18 U1_PD1.4 U1_PD2.4 U1_PD3.4 U1_PD4.4 U1_PD5.4 U1_PD6.4 U1_PD7.4 U1_PD8.4 U1_PD9.4 U1_PD10.4 U1_PD11.4 U1_PD12.4 U1_PD13.4 U1_PD14.4 U1_PD15.4 U1_PD16.4 U1_PD17.4 U1_PD18.4 U1_PD19.4 U1_PD20.4 U1_PD21.4 U1_PD22.4 U1_PD23.4 U1_PD24.4 U1_PD25.4 U1_PD26.4 U1_PD27.4 U1_PD28.4 U1_PD29.4 U1_PD30.4 U1_PD31.4 U1_PD32.4 | length 4812.2
  TopLayer w4: v1(6800,13620) 6800,13605 6805,13600 U1_PD1.4@6862.35,13600 ; v1(6800,14280) 6800,14265 6805,14260 U1_PD9.4@6862.35,14260 ; v1(6800,14940) 6800,14925 6805,14920 U1_PD17.4@6862.35,14920 ; v1(6800,15600) 6800,15585 6805,15580 U1_PD25.4@6862.35,15580 ; v1(7540,13620) 7540,13605 7545,13600 U1_PD2.4@7602.35,13600 ; v1(7540,14280) 7540,14265 7545,14260 U1_PD10.4@7602.35,14260 ; v1(7540,14940) 7540,14925 7545,14920 U1_PD18.4@7602.35,14920 ; v1(7540,15600) 7540,15585 7545,15580 U1_PD26.4@7602.35,15580 ; v1(8280,13620) 8280,13605 8285,13600 U1_PD3.4@8342.35,13600 ; v1(8280,14280) 8280,14265 8285,14260 U1_PD11.4@8342.35,14260 ; v1(8280,14940) 8280,14925 8285,14920 U1_PD19.4@8342.35,14920 ; v1(8280,15600) 8280,15585 8285,15580 U1_PD27.4@8342.35,15580 ; v1(9020,13620) 9020,13605 9025,13600 U1_PD4.4@9082.35,13600 ; v1(9020,14280) 9020,14265 9025,14260 U1_PD12.4@9082.35,14260 ; v1(9020,14940) 9020,14925 9025,14920 U1_PD20.4@9082.35,14920 ; v1(9020,15600) 9020,15585 9025,15580 U1_PD28.4@9082.35,15580
  MidLayer1 w18: v1(6335,13775) 6335,13620 v1(6720,13620) ; v1(6335,14435) 6335,14280 v1(6720,14280) ; v1(6335,15095) 6335,14940 v1(6720,14940) ; v1(6335,15755) 6335,15600 v1(6720,15600)
  BottomLayer w4: U1_PD8.4@6657.65,13600 6715,13600 6720,13605 v1(6720,13620) ; U1_PD16.4@6657.65,14260 6715,14260 6720,14265 v1(6720,14280) ; U1_PD24.4@6657.65,14920 6715,14920 6720,14925 v1(6720,14940) ; U1_PD32.4@6657.65,15580 6715,15580 6720,15585 v1(6720,15600) ; U1_PD7.4@7397.65,13600 7455,13600 7460,13605 v1(7460,13620) ; U1_PD15.4@7397.65,14260 7455,14260 7460,14265 v1(7460,14280) ; U1_PD23.4@7397.65,14920 7455,14920 7460,14925 v1(7460,14940) ; U1_PD31.4@7397.65,15580 7455,15580 7460,15585 v1(7460,15600) ; U1_PD6.4@8137.65,13600 8195,13600 8200,13605 v1(8200,13620) ; U1_PD14.4@8137.65,14260 8195,14260 8200,14265 v1(8200,14280) ; U1_PD22.4@8137.65,14920 8195,14920 8200,14925 v1(8200,14940) ; U1_PD30.4@8137.65,15580 8195,15580 8200,15585 v1(8200,15600) ; U1_PD5.4@8877.65,13600 8935,13600 8940,13605 v1(8940,13620) ; U1_PD13.4@8877.65,14260 8935,14260 8940,14265 v1(8940,14280) ; U1_PD21.4@8877.65,14920 8935,14920 8940,14925 v1(8940,14940) ; U1_PD29.4@8877.65,15580 8935,15580 8940,15585 v1(8940,15600)
  BottomLayer w8: JP2_BANK1.18@6333.98,13747.32 v1@6333.98,13775 ; JP2_BANK2.18@6333.98,14407.32 v1@6333.98,14435 ; JP2_BANK3.18@6333.98,15067.32 v1@6333.98,15095 ; JP2_BANK4.18@6333.98,15727.32 v1@6333.98,15755
VSSM5: JP1.5 JP1.6 U1_PD1.11 U1_PD2.11 U1_PD3.11 U1_PD4.11 U1_PD5.11 U1_PD6.11 U1_PD7.11 U1_PD8.11 U1_PD9.11 U1_PD10.11 U1_PD11.11 U1_PD12.11 U1_PD13.11 U1_PD14.11 U1_PD15.11 U1_PD16.11 U1_PD17.11 U1_PD18.11 U1_PD19.11 U1_PD20.11 U1_PD21.11 U1_PD22.11 U1_PD23.11 U1_PD24.11 U1_PD25.11 U1_PD26.11 U1_PD27.11 U1_PD28.11 U1_PD29.11 U1_PD30.11 U1_PD31.11 U1_PD32.11 | length 15384.4
  TopLayer w4: U1_PD1.11@6657.63,13600 6715,13600 6720,13595 v1(6720,13580) ; U1_PD9.11@6657.63,14260 6715,14260 6720,14255 v1(6720,14240) ; U1_PD17.11@6657.63,14920 6715,14920 6720,14915 v1(6720,14900) ; U1_PD25.11@6657.63,15580 6715,15580 6720,15575 v1(6720,15560) ; U1_PD2.11@7397.63,13600 7455,13600 7460,13595 v1(7460,13580) ; U1_PD10.11@7397.63,14260 7455,14260 7460,14255 v1(7460,14240) ; U1_PD18.11@7397.63,14920 7455,14920 7460,14915 v1(7460,14900) ; U1_PD26.11@7397.63,15580 7455,15580 7460,15575 v1(7460,15560) ; U1_PD3.11@8137.63,13600 8195,13600 8200,13595 v1(8200,13580) ; U1_PD11.11@8137.63,14260 8195,14260 8200,14255 v1(8200,14240) ; U1_PD19.11@8137.63,14920 8195,14920 8200,14915 v1(8200,14900) ; U1_PD27.11@8137.63,15580 8195,15580 8200,15575 v1(8200,15560) ; U1_PD4.11@8877.63,13600 8935,13600 8940,13595 v1(8940,13580) ; U1_PD12.11@8877.63,14260 8935,14260 8940,14255 v1(8940,14240) ; U1_PD20.11@8877.63,14920 8935,14920 8940,14915 v1(8940,14900) ; U1_PD28.11@8877.63,15580 8935,15580 8940,15575 v1(8940,15560)
  MidLayer1 w18: v1(6720,13580) v1(6800,13580) v1(7460,13580) v1(7540,13580) v1(8200,13580) v1(8280,13580) v1(8940,13580) v1(9020,13580) v1(9370,13580) ; v1(6720,14240) v1(6800,14240) v1(7460,14240) v1(7540,14240) v1(8200,14240) v1(8280,14240) v1(8940,14240) v1(9020,14240) v1(9370,14240) ; v1(6720,14900) v1(6800,14900) v1(7460,14900) v1(7540,14900) v1(8200,14900) v1(8280,14900) v1(8940,14900) v1(9020,14900) v1(9370,14900) ; v1(6720,15560) v1(6800,15560) v1(7460,15560) v1(7540,15560) v1(8200,15560) v1(8280,15560) v1(8940,15560) v1(9020,15560) v1(9370,15560)
  BottomLayer w4: v1(6800,13580) 6800,13595 6805,13600 U1_PD8.11@6862.37,13600 ; v1(6800,14240) 6800,14255 6805,14260 U1_PD16.11@6862.37,14260 ; v1(6800,14900) 6800,14915 6805,14920 U1_PD24.11@6862.37,14920 ; v1(6800,15560) 6800,15575 6805,15580 U1_PD32.11@6862.37,15580 ; v1(7540,13580) 7540,13595 7545,13600 U1_PD7.11@7602.37,13600 ; v1(7540,14240) 7540,14255 7545,14260 U1_PD15.11@7602.37,14260 ; v1(7540,14900) 7540,14915 7545,14920 U1_PD23.11@7602.37,14920 ; v1(7540,15560) 7540,15575 7545,15580 U1_PD31.11@7602.37,15580 ; v1(8280,13580) 8280,13595 8285,13600 U1_PD6.11@8342.37,13600 ; v1(8280,14240) 8280,14255 8285,14260 U1_PD14.11@8342.37,14260 ; v1(8280,14900) 8280,14915 8285,14920 U1_PD22.11@8342.37,14920 ; v1(8280,15560) 8280,15575 8285,15580 U1_PD30.11@8342.37,15580 ; v1(9020,13580) 9020,13595 9025,13600 U1_PD5.11@9082.37,13600 ; v1(9020,14240) 9020,14255 9025,14260 U1_PD13.11@9082.37,14260 ; v1(9020,14900) 9020,14915 9025,14920 U1_PD21.11@9082.37,14920 ; v1(9020,15560) 9020,15575 9025,15580 U1_PD29.11@9082.37,15580
  BottomLayer w18: v1(9370,13580) v1(9370,14240) 9370,14480 JP1.5@9445,14555 JP1.6@9445,14655 9370,14730 v1(9370,14900) v1@9370,15555 ; JP1.6@9430,14655 9430,14555 JP1.5@9435,14555 ; JP1.5@9460,14555 JP1.6@9460,14655
pads on no net: JP2_BANK1.19 JP2_BANK1.20 JP2_BANK2.19 JP2_BANK2.20 JP2_BANK3.19 JP2_BANK3.20 JP2_BANK4.19 JP2_BANK4.20 U1_PD1.12 U1_PD1.13 U1_PD1.14 U1_PD2.12 U1_PD2.13 U1_PD2.14 U1_PD3.12 U1_PD3.13 U1_PD3.14 U1_PD4.12 U1_PD4.13 U1_PD4.14 U1_PD5.12 U1_PD5.13 U1_PD5.14 U1_PD6.12 U1_PD6.13 U1_PD6.14 U1_PD7.12 U1_PD7.13 U1_PD7.14 U1_PD8.12 U1_PD8.13 U1_PD8.14 U1_PD9.12 U1_PD9.13 U1_PD9.14 U1_PD10.12 U1_PD10.13 U1_PD10.14 U1_PD11.12 U1_PD11.13 U1_PD11.14 U1_PD12.12 U1_PD12.13 U1_PD12.14 U1_PD13.12 U1_PD13.13 U1_PD13.14 U1_PD14.12 U1_PD14.13 U1_PD14.14 U1_PD15.12 U1_PD15.13 U1_PD15.14 U1_PD16.12 U1_PD16.13 U1_PD16.14 U1_PD17.12 U1_PD17.13 U1_PD17.14 U1_PD18.12 U1_PD18.13 U1_PD18.14 U1_PD19.12 U1_PD19.13 U1_PD19.14 U1_PD20.12 U1_PD20.13 U1_PD20.14 U1_PD21.12 U1_PD21.13 U1_PD21.14 U1_PD22.12 U1_PD22.13 U1_PD22.14 U1_PD23.12 U1_PD23.13 U1_PD23.14 U1_PD24.12 U1_PD24.13 U1_PD24.14 U1_PD25.12 U1_PD25.13 U1_PD25.14 U1_PD26.12 U1_PD26.13 U1_PD26.14 U1_PD27.12 U1_PD27.13 U1_PD27.14 U1_PD28.12 U1_PD28.13 U1_PD28.14 U1_PD29.12 U1_PD29.13 U1_PD29.14 U1_PD30.12 U1_PD30.13 U1_PD30.14 U1_PD31.12 U1_PD31.13 U1_PD31.14 U1_PD32.12 U1_PD32.13 U1_PD32.14

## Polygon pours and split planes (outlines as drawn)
GND on GROUND (split plane): 9474.93,14915.1 9405.1,14915.1 9405.1,15650 9404.71,15651.95 9403.6,15653.6 9401.95,15654.71 9400,15655.1 6690,15655.1 6688.05,15654.71 6686.4,15653.6 6685.29,15651.95 6684.9,15650 6684.9,15580 6685.29,15578.05 6686.4,15576.4 6688.05,15575.29 6690,15574.9 9304.9,15574.9 9304.9,14995.1 6690,14995.1 6688.05,14994.71 6686.4,14993.6 6685.29,14991.95 6684.9,14990 6684.9,14920 6685.29,14918.05 6686.4,14916.4 6688.05,14915.29 6690,14914.9 9304.9,14914.9 9304.9,14335.1 6690,14335.1 6688.05,14334.71 6686.4,14333.6 6685.29,14331.95 6684.9,14330 6684.9,14260 6685.29,14258.05 6686.4,14256.4 6688.05,14255.29 6690,14254.9 9304.9,14254.9 9304.9,13675.1 6690,13675.1 6688.05,13674.71 6686.4,13673.6 6685.29,13671.95 6684.9,13670 6684.9,13600 6685.29,13598.05 6686.4,13596.4 6688.05,13595.29 6690,13594.9 9400,13594.9 9401.95,13595.29 9403.6,13596.4 9404.71,13598.05 9405.1,13600 9405.1,14699.9 9474.93,14699.9 9474.93,13230.07 6175.07,13230.07 6175.07,15924.93 9474.93,15924.93
VCC5 on GROUND (split plane): 9394.9,14910 9395.29,14908.05 9396.4,14906.4 9398.05,14905.29 9400,14904.9 9474.93,14904.9 9474.93,14710.1 9400,14710.1 9398.05,14709.71 9396.4,14708.6 9395.29,14706.95 9394.9,14705 9394.9,13605.1 6695.1,13605.1 6695.1,13664.9 9310,13664.9 9311.95,13665.29 9313.6,13666.4 9314.71,13668.05 9315.1,13670 9315.1,14260 9314.71,14261.95 9313.6,14263.6 9311.95,14264.71 9310,14265.1 6695.1,14265.1 6695.1,14324.9 9310,14324.9 9311.95,14325.29 9313.6,14326.4 9314.71,14328.05 9315.1,14330 9315.1,14920 9314.71,14921.95 9313.6,14923.6 9311.95,14924.71 9310,14925.1 6695.1,14925.1 6695.1,14984.9 9310,14984.9 9311.95,14985.29 9313.6,14986.4 9314.71,14988.05 9315.1,14990 9315.1,15580 9314.71,15581.95 9313.6,15583.6 9311.95,15584.71 9310,15585.1 6695.1,15585.1 6695.1,15644.9 9394.9,15644.9

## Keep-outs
KeepOutLayer:
  lines w10: 6155,13210 6155,15945 9495,15945 9495,13210 6156,13210

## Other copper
GROUND (plane layer: these items are gaps in the copper):
  lines w10: 9505,14705 9400,14705 9400,13600 6690,13600 6690,13670 9310,13670 9310,14260 6690,14260 6690,14330 9310,14330 9310,14920 6690,14920 6690,14990 9310,14990 9310,15580 6690,15580 6690,15650 9400,15650 9400,14910 9505,14910

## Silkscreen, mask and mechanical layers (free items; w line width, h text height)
Mechanical4:
  lines w10: 6155,13210 6155,15945 9495,15945 9495,13210 6155,13210

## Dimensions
6155,13210 to 6155,15945 on Mechanical1
6155,13210 to 9495,13210 on KeepOutLayer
